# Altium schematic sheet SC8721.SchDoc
size A4
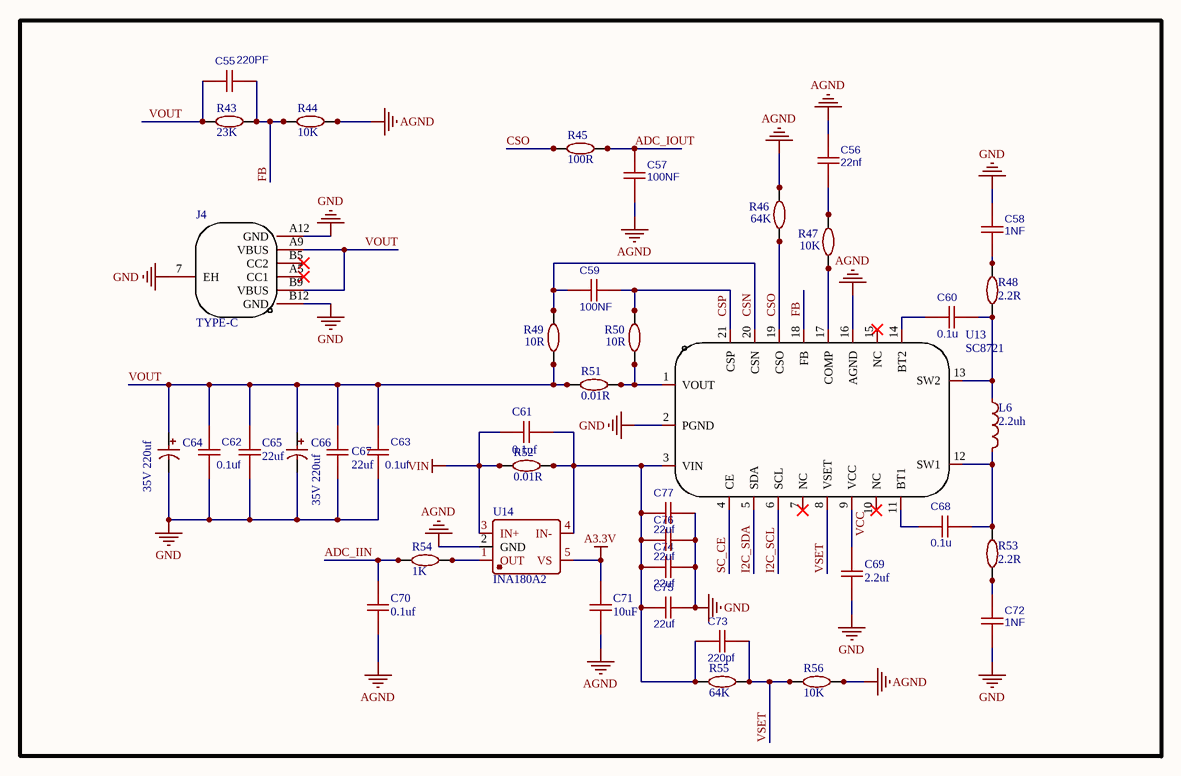
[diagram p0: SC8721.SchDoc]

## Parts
C55  220PF  [C0402]
C56  22nf  [C0402]
C57  100NF  [C0402]
C58  1NF  [C0603]
C59  100NF  [C0402]
C60  0.1u  [C0402]
C61  0.1uf  [C0402]
C62  0.1uf  [C1206]
C63  0.1uf  [C0603]
C64  35V 220uf  [8*12mm]
C65  22uf  [C0603]
C66  35V 220uf  [8*12mm]
C67  22uf  [C1206]
C68  0.1u  [C0402]
C69  2.2uf  [C0402]
C70  0.1uf  [C0402]
C71  10uF  [C0402 - duplicate]
C72  1NF  [C0603]
C73  220pf  [C0402]
C74  22uf  [C0805]
C75  22uf  [C0805]
C76  22uf  [C0805]
C77  22uf  [C0805]
J4  TYPE-C  [TYPEC-8A]
L6  2.2uh  [2.2uh]
R43  23K  [R0402]
R44  10K  [R0402]
R45  100R  [R0402]
R46  64K  [R0402]
R47  10K  [R0402]
R48  2.2R  [R0805]
R49  10R  [R0402]
R50  10R  [R0402]
R51  0.01R  [R1206]
R52  0.01R  [R1206]
R53  2.2R  [R0805]
R54  1K  [R0402]
R55  64K  [R0402]
R56  10K  [R0402]
U13  SC8721  [QFN-21(4x4)]
U14  INA180A2  [SOT-23-5]

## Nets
A3.3V: C71.2 U14.5(VS)
AGND: C56.2 C57.1 C70.2 C71.1 R44.2 R46.1 R56.2 U13.16(AGND) U14.2(GND)
GND: C58.2 C62.2 C63.2 C64.2 C65.1 C66.2 C67.1 C69.1 C72.2 C74.1 C75.1 C76.1 C77.1 J4.7(EH) J4.A12(GND) J4.B12(GND) U13.2(PGND)
VIN: C61.2 R52.1 U14.3(IN+)
ADC_IIN: C70.1 R54.2
ADC_IOUT: C57.2 R45.2
CSN: C59.2 R49.1 U13.20(CSN)
CSO: R45.1 R46.2 U13.19(CSO)
CSP: C59.1 R50.1 U13.21(CSP)
FB: C55.1 R43.2 R44.1 U13.18(FB)
I2C_SCL: U13.6(SCL)
I2C_SDA: U13.5(SDA)
SC_CE: U13.4(CE)
VCC: C69.2 U13.9(VCC)
VOUT: C55.2 C62.1 C63.1 C64.1 C65.2 C66.1 C67.2 J4.A9(VBUS) J4.B9(VBUS) R43.1 R49.2 R51.1
VSET: C73.1 R55.2 R56.1 U13.8(VSET)
NetC56_1: C56.1 R47.1
NetC58_1: C58.1 R48.1
NetC60_1: C60.1 L6.1 R48.2 U13.13(SW2)
NetC60_2: C60.2 U13.14(BT2)
NetC61_1: C61.1 C73.2 C74.2 C75.2 C76.2 C77.2 R52.2 R55.1 U13.3(VIN) U14.4(IN-)
NetC68_1: C68.1 L6.2 R53.1 U13.12(SW1)
NetC68_2: C68.2 U13.11(BT1)
NetC72_1: C72.1 R53.2
NetR47_2: R47.2 U13.17(COMP)
NetR50_2: R50.2 R51.2 U13.1(VOUT)
NetR54_1: R54.1 U14.1(OUT)

Not connected (* = marked no-connect by the designer): J4 A5(CC1)* B5(CC2)*; U13 7(NC)* 10(NC)* 15(NC)*

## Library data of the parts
C55-C59 C62 C63 C72-C77 = 1n: nameAlias: Value(F); Contributor: LCEDA_Lib
C60 C68 = 0.1u: nameAlias: Value(F); Contributor: LCEDA_Lib
C61 C65 C67 C69-C71 = 贴片电容
C64 C66 = 贴片电解电容
L6 = 贴片电感
R43-R56 = 贴片电阻
U14 = INA180A1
